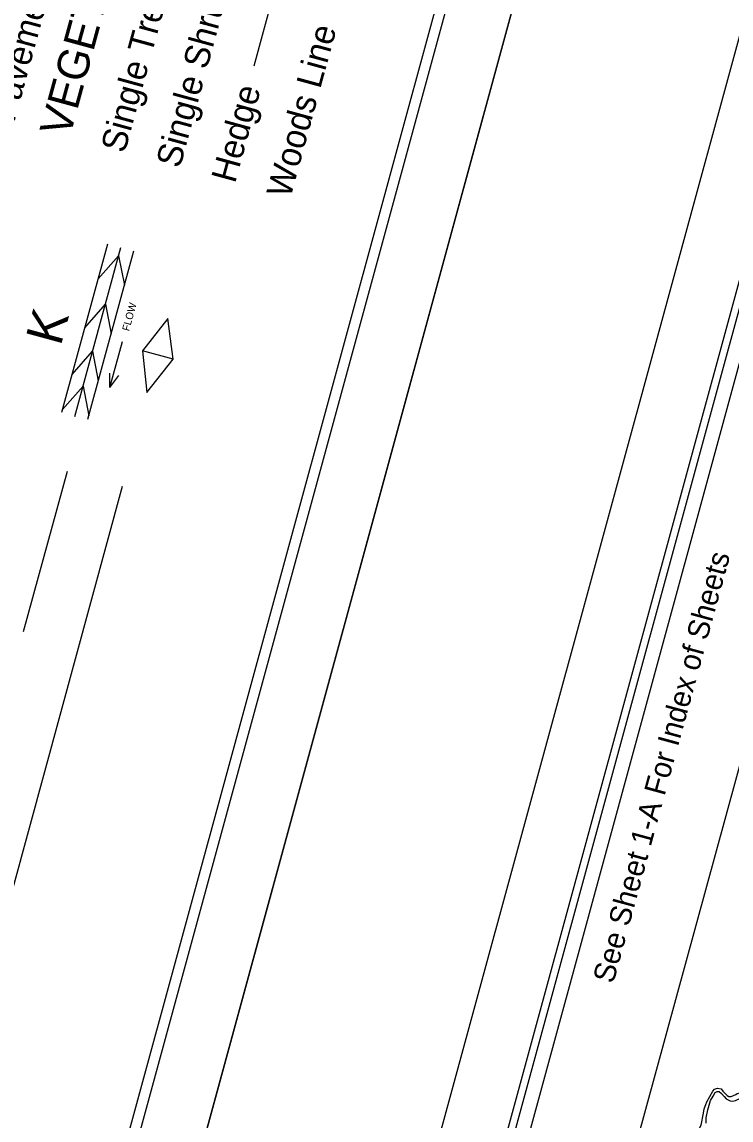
# Model space of a CAD drawing. Extents: x 2076126 to 2079903, y 925480 to 928006.
# Drawn here: x 2078319.5 to 2078567.3, y 926019.2 to 926403.1 of the extents above; entities that cross this region are included whole.
import ezdxf

# ---------------------------------------------------------------- set-up
doc = ezdxf.new("R2010")
doc.units = 0
for name, color, linetype in [('Default', 7, 'Continuous'), ('Old_Level_59', 7, 'Continuous'), ('Sheet Cutting Line CELL', 7, 'Continuous'), ('Sheet Plot Border Inside CELL', 7, 'Continuous'), ('Sheet Plot Border Outside CELL', 7, 'Continuous'), ('Sheet Symbology CELL', 7, 'Continuous'), ('Sheet Title CELL', 7, 'Continuous')]:
    doc.layers.add(name, color=color, linetype=linetype)

msp = doc.modelspace()

# ---------------------------------------------------------------- linework, layer by layer
at = {"layer": 'Default'}
msp.add_line((2078643.24, 926410.74), (2078526.08, 925981.22), dxfattribs=at)
at = {"layer": 'Old_Level_59'}
for points in [[(2078558.61, 926018.15), (2078558.62, 926020.07), (2078559.24, 926022.86), (2078560.12, 926026.04), (2078561.07, 926027.64), (2078561.79, 926028.86), (2078562.48, 926029.25), (2078563.12, 926029.25), (2078564.03, 926028.54), (2078564.89, 926027.46), (2078565.59, 926026.63), (2078567.06, 926025.99), (2078567.91, 926025.81), (2078568.88, 926026.04), (2078570.58, 926026.94), (2078571.78, 926027.31), (2078573.49, 926028.03), (2078575.98, 926030.24), (2078578.56, 926032.35), (2078580.43, 926034.76), (2078580.99, 926036.16), (2078580.85, 926036.66)], [(2078558.86, 926025.61), (2078560.92, 926029.39), (2078561.59, 926030.02), (2078562.59, 926030.39), (2078563.82, 926030.11), (2078564.41, 926029.39), (2078565.95, 926027.81), (2078566.5, 926027.45), (2078567.32, 926027.46), (2078569, 926028.18), (2078569.5, 926028.52), (2078570.38, 926028.77), (2078571.34, 926028.88), (2078573.36, 926029.66), (2078576.49, 926032.09), (2078578.94, 926034.07), (2078579.57, 926034.72), (2078579.77, 926035.12), (2078579.51, 926036.47), (2078579.61, 926036.99)], [(2078542.68, 926011.91), (2078545.19, 926011.84), (2078548.14, 926012.07), (2078552.42, 926013.28), (2078555.05, 926014.95), (2078555.85, 926015.55), (2078556.93, 926017.49), (2078557.71, 926021.62), (2078557.92, 926023.22), (2078558.48, 926024.64), (2078558.86, 926025.61)]]:
    msp.add_lwpolyline(points, dxfattribs=at)
at = {"layer": 'Sheet Cutting Line CELL'}
msp.add_line((2078321.04, 925784.51), (2078764.17, 927409.16), dxfattribs=at)
at = {"layer": 'Sheet Plot Border Inside CELL'}
for points in [[(2078302.8, 925802.96), (2078741.33, 927410.72), (2077723.41, 927688.37), (2077284.89, 926080.6)], [(2079441.8, 925498.58), (2079880.32, 927106.35), (2078862.41, 927383.99), (2078423.88, 925776.22)]]:
    msp.add_lwpolyline(points, close=True, dxfattribs=at)
at = {"layer": 'Sheet Plot Border Outside CELL'}
for points in [[(2078321.04, 925784.51), (2078764.17, 927409.16), (2077702.94, 927698.61), (2077259.81, 926073.96)], [(2078841.94, 927394.24), (2078398.8, 925769.59), (2079460.02, 925480.14), (2079903.16, 927104.79)]]:
    msp.add_lwpolyline(points, close=True, dxfattribs=at)
at = {"layer": 'Sheet Symbology CELL'}
for p, q in [((2078456.51, 926592.79), (2078400.54, 926387.6)), ((2078333.43, 926266.7), (2078349.49, 926325.56)), ((2078338, 926265.19), (2078354.12, 926324.3)), ((2078342.55, 926264.21), (2078358.61, 926323.08)), ((2078346.14, 926313.3), (2078353.3, 926321.3)), ((2078353.3, 926321.3), (2078355.33, 926311.07)), ((2078341.48, 926296.19), (2078348.69, 926304.4)), ((2078348.69, 926304.4), (2078350.69, 926294.04)), ((2078370.53, 926299.47), (2078361.69, 926288.08)), ((2078372.35, 926285.17), (2078370.53, 926299.47)), ((2078350.25, 926275.33), (2078354.63, 926291.39)), ((2078337.02, 926279.83), (2078344.22, 926288.01)), ((2078344.22, 926288.01), (2078346.21, 926277.65)), ((2078372.35, 926285.17), (2078361.69, 926288.08)), ((2078361.69, 926288.08), (2078363.21, 926273.6)), ((2078363.21, 926273.6), (2078372.35, 926285.17)), ((2078350.25, 926275.33), (2078350.21, 926280.32)), ((2078350.25, 926275.33), (2078353.39, 926279.45)), ((2078333.67, 926267.57), (2078340.88, 926275.75)), ((2078340.88, 926275.75), (2078342.86, 926265.35)), ((2078335.3, 926245.99), (2078319.99, 926189.87)), ((2078354.6, 926240.73), (2078307.16, 926066.81))]:
    msp.add_line(p, q, dxfattribs=at)
msp.add_lwpolyline([(2077722.58, 927675.63), (2077327.87, 926228.5), (2078339.88, 925952.47), (2078734.6, 927399.6)], close=True, dxfattribs=at)
at = {"layer": 'Sheet Title CELL'}
for points in [[(2078858.95, 927361.63), (2078469.48, 925933.76)], [(2078862.46, 927355.47), (2078488.8, 925985.53)]]:
    msp.add_lwpolyline(points, dxfattribs=at)

# ---------------------------------------------------------------- texts
at = {"layer": 'Sheet Symbology CELL'}
for s, height, p in [('Pavement Removal', 8.75, (2078316.83, 926367.74)), ('VEGETATION:', 11, (2078336.21, 926362.45)), ('Single Tree', 8.75, (2078355.4, 926356.92)), ('Single Shrub', 8.75, (2078374.7, 926351.66)), ('Woods Line', 8.75, (2078413.29, 926341.14)), ('Hedge', 8.75, (2078393.99, 926346.4)), ('K', 12.75, (2078333.05, 926289.52)), ('FLOW', 2.593, (2078356.97, 926294.84))]:
    msp.add_text(s, height=height, rotation=74.7434, dxfattribs=at).set_placement(p)
at = {"layer": 'Sheet Title CELL'}
msp.add_text('See Sheet 1-A For Index of Sheets', height=7.5, rotation=74.7434, dxfattribs=at).set_placement((2078526.16, 926066.65))

doc.saveas('drawing.dxf')
